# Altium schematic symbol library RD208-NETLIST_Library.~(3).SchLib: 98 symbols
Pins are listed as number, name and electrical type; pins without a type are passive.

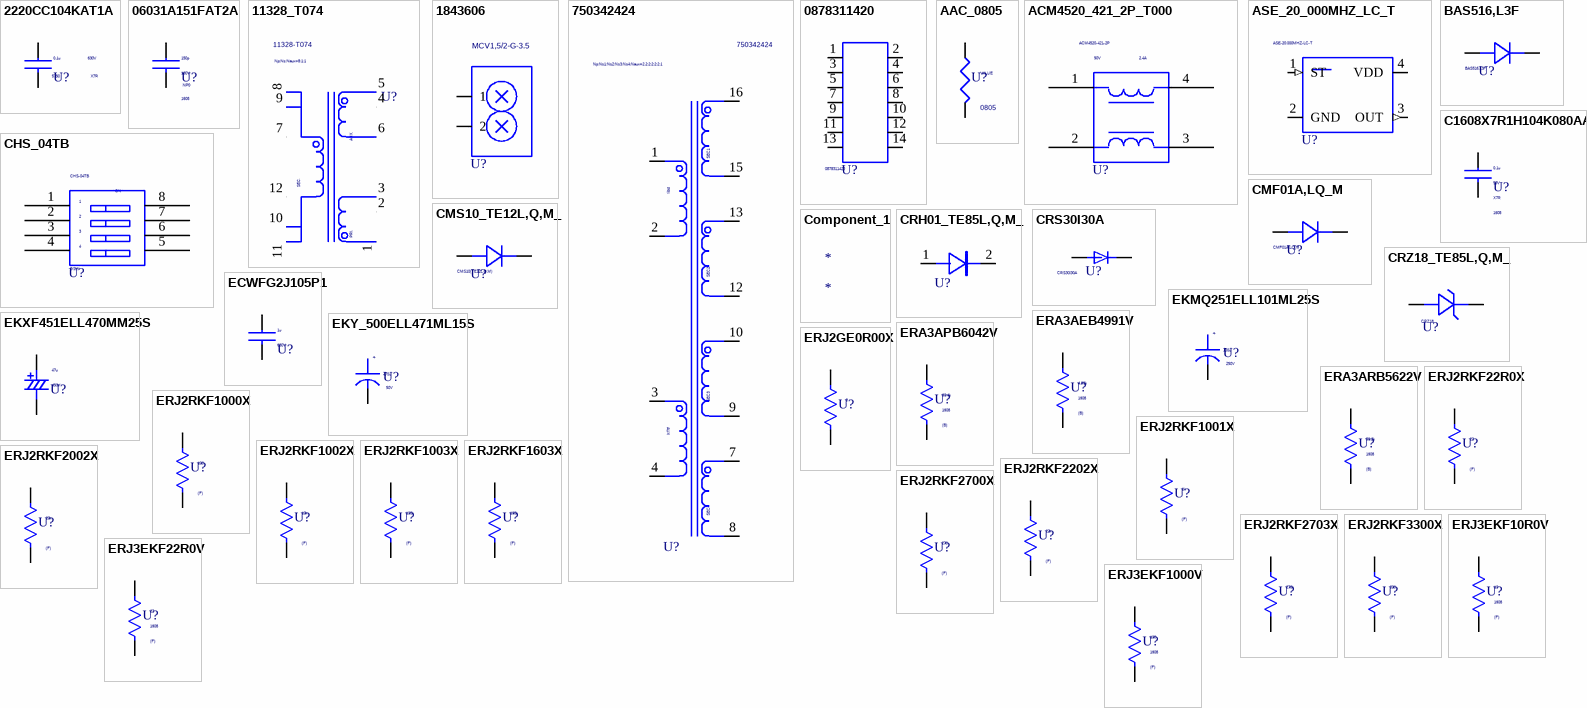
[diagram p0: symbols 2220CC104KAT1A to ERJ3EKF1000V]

## 2220CC104KAT1A
designator U?  VAL2: 630V  SIZECODESMD: 5750  VALUE4: X7R  VAL1: 0.1u  (hidden comment: 2220CC104KAT1A)
MANUFACTURER: AVX; ITEM: CAP Ceramic; TIME: 08:44:47; UPDATEUSER: t5459927; SAVECOUNT: 1; OriginalSymbolOrigin: (0,0); Altium-Right: 20; Altium-Bottom: 10
pins: 1, 2

## 06031A151FAT2A
designator U?  VAL2: 100V  SIZECODESMD: 1608  VALUE4: NP0  VAL1: 150p  (hidden comment: 06031A151FAT2A)
MANUFACTURER: AVX; ITEM: CAP Ceramic; TIME: 08:44:46; UPDATEUSER: t5459927; SAVECOUNT: 1; OriginalSymbolOrigin: (0,0); Altium-Right: 20; Altium-Bottom: 10
pins: 1, 2

## 11328_T074
designator U?  VAL2: Np:Ns:Naux=8:1:1  VAL1: 11328-T074  (hidden comment: 11328_T074)
MANUFACTURER: SUMIDA; ITEM: Transformer; TIME: 08:44:47; UPDATEUSER: PS4_common_PC; UPDATETIME: 15:04:11; SAVECOUNT: 3; SAVEAREA0: -40366,-32840,49907,8293; OriginalSymbolOrigin: (-2540,2540); Altium-Right: 60; Altium-Bottom: 120
pins: 1, 2, 3, 4, 5, 6, 7, 8, 9, 10, 11, 12

## 1843606
designator U?  SCH_NAME: MCV1,5/2-G-3.5  (hidden comment: 1843606)
MANUFACTURER: PHOENIX CONTACT; ITEM: Connector 2Pin Terminal Block; TIME: 08:44:48; UPDATEUSER: PS4_common_PC; UPDATETIME: 15:46:31; SAVECOUNT: 2; SAVEAREA0: -7641,-15544,14757,852; OriginalSymbolOrigin: (0,0); Altium-Right: 40; Altium-Bottom: 60
pins: 1, 2

## 750342424
designator U?  VAL2: Np:Ns1:Ns2:Ns3:Ns4:Naux=2.2:2:2:2:2:1  (hidden comment: 750342424)
MANUFACTURER: WURTH; ITEM: Transformer; TIME: 08:44:46; UPDATEUSER: t5459927; SAVECOUNT: 1; OriginalSymbolOrigin: (0,2540); Altium-Right: 40; Altium-Bottom: 310
pins: 1, 2, 3, 4, 7, 8, 9, 10, 12, 13, 15, 16

## 0878311420
designator U?
MANUFACTURER: Molex; ITEM: Connector; TIME: 08:44:46; UPDATEUSER: PS4_common_PC; UPDATETIME: 10:48:07; SAVECOUNT: 2; SAVEAREA0: -11456,-20726,18408,1136; OriginalSymbolOrigin: (0,0); Altium-Right: 30; Altium-Bottom: 80
pins: 1, 2, 3, 4, 5, 6, 7, 8, 9, 10, 11, 12, 13, 14

## AAC_0805
designator U?  SIZE: 0805  VAL1: VALUE  (hidden comment: AAC_0805)
7TH PART FIELD: RES.,; 4TH PART FIELD: VISHAY,; 3RD PART FIELD: CHIP; 2ND PART FIELD: 1-5%; 5TH PART FIELD: CRCW0805---RT6; 1ST PART FIELD: 1/8W; TIME: 08:44:45; UPDATEUSER: t5459927; SAVECOUNT: 1; OriginalSymbolOrigin: (0,0); Altium-Right: 20; Altium-Bottom: 30
pins: 1, 2

## ACM4520_421_2P_T000
designator U?  VAL2: 2.4A  VAL1: 50V  SCH_NAME: ACM4520-421-2P  (hidden comment: ACM4520_421_2P_T000)
MANUFACTURER: TDK; ITEM: Filter; COMP: ACM4520-421-2P-T000; TIME: 08:44:48; UPDATEUSER: PS4_common_PC; UPDATETIME: 15:46:48; SAVECOUNT: 2; SAVEAREA0: -11402,-15649,23384,1144; OriginalSymbolOrigin: (0,0); Altium-Right: 50; Altium-Bottom: 60
pins: 1 B, 2 CB, 3 PSG, 4 CG4

## ASE_20_000MHZ_LC_T
designator U?  VAL1: ASE-20.000MHZ-LC-T  (hidden comment: ASE_20_000MHZ_LC_T)
MANUFACTURER: Abracon; ITEM: Crystal  Oscillator; VAL2: 20.0MHz; SIZECODESMD: 3225; VALUE4: 50ppm; TIME: 08:44:46; UPDATEUSER: PS4_common_PC; UPDATETIME: 16:08:33; SAVECOUNT: 3; SAVEAREA0: -31083,-23837,46439,11486; OriginalSymbolOrigin: (0,0); Altium-Right: 60; Altium-Bottom: 50
pins: 1 ST (in), 2 GND, 3 OUT (out), 4 VDD

## BAS516,L3F
designator U?
MANUFACTURER: TOSHIBA; ITEM: DIODE; TIME: 08:44:45; UPDATEUSER: t5459927; SAVECOUNT: 1; OriginalSymbolOrigin: (0,0); Altium-Right: 30; Altium-Bottom: 20
pins: A ANODE, K CATHODE

## C1608X7R1H104K080AA
designator U?  VAL2: 50V  SIZECODESMD: 1608  VALUE4: X7R  VAL1: 0.1u  (hidden comment: C1608X7R1H104K080AA)
MANUFACTURER: TDK; ITEM: CAP Ceramic; TIME: 08:44:45; UPDATEUSER: t5459927; SAVECOUNT: 1; OriginalSymbolOrigin: (0,0); Altium-Right: 20; Altium-Bottom: 10
pins: 1, 2

## CHS_04TB
designator U?  VAL1: DSW  SCH_NAME: CHS-04TB  (hidden comment: CHS_04TB)
MANUFACTURER: COPAL; ITEM: DIP Switch 4P; VAL2: 50V 100mA; TIME: 08:44:46; UPDATEUSER: PS4_common_PC; UPDATETIME: 10:48:35; SAVECOUNT: 2; SAVEAREA0: -8722,-16798,20771,4793; OriginalSymbolOrigin: (0,0); Altium-Right: 50
pins: 1, 2, 3, 4, 5, 6, 7, 8

## CMF01A,LQ_M
designator U?  VAL1: CMF01A,LQ(M  (hidden comment: CMF01A,LQ_M)
MANUFACTURER: TOSHIBA; ITEM: DIODE; TIME: 08:44:46; UPDATEUSER: t5459927; SAVECOUNT: 1; OriginalSymbolOrigin: (0,0); Altium-Right: 30; Altium-Bottom: 20
pins: A ANODE, K CATHODE

## CMS10_TE12L,Q,M_
designator U?  VAL1: CMS10(TE12L,Q,M)  (hidden comment: CMS10_TE12L,Q,M_)
MANUFACTURER: TOSHIBA; ITEM: DIODE; TIME: 08:44:46; UPDATEUSER: t5459927; SAVECOUNT: 1; OriginalSymbolOrigin: (0,0); Altium-Right: 30; Altium-Bottom: 20
pins: A ANODE, K CATHODE

## Component_1
designator *

## CRH01_TE85L,Q,M_
designator U?  (value not drawn)
MANUFACTURER: TOSHIBA; ITEM: DIODE; COMP: CRH01(TE85L,Q,M); TIME: 08:44:47; UPDATEUSER: t5459927; SAVECOUNT: 1; OriginalSymbolOrigin: (0,0); Altium-Right: 30; Altium-Bottom: 20
pins: 1 A, 2 C

## CRS30I30A
designator U?
MANUFACTURER: TOSHIBA; ITEM: DIODE; TIME: 08:44:48; UPDATEUSER: t5459927; SAVECOUNT: 1; OriginalSymbolOrigin: (0,0); Altium-Right: 20
pins: A ANODE, K CATHODE

## CRZ18_TE85L,Q,M_
designator U?  VAL1: CRZ18  (hidden comment: CRZ18_TE85L,Q,M_)
MANUFACTURER: TOSHIBA; COMP: CRZ18(TE85L,Q,M); ITEM: DIODE Zener; TIME: 08:44:47; UPDATEUSER: t5459927; SAVECOUNT: 1; OriginalSymbolOrigin: (0,0); Altium-Right: 30; Altium-Bottom: 20
pins: A ANODE, K CATHODE

## ECWFG2J105P1
designator U?  VAL2: 630V  VAL1: 1u  (hidden comment: ECWFG2J105P1)
MANUFACTURER: PANASONIC; ITEM: CAP Film; TIME: 08:44:47; UPDATEUSER: t5459927; SAVECOUNT: 1; OriginalSymbolOrigin: (0,0); Altium-Right: 20; Altium-Bottom: 10
pins: 1, 2

## EKMQ251ELL101ML25S
designator U?  VAL2: 250V  VAL1: 100u  (hidden comment: EKMQ251ELL101ML25S)
MANUFACTURER: Nippon Chemi-Con; ITEM: CAP ALUM; TIME: 08:44:45; UPDATEUSER: t5459927; SAVECOUNT: 1; OriginalSymbolOrigin: (0,2540); Altium-Right: 20
pins: 1, 2

## EKXF451ELL470MM25S
designator U?  VAL2: 450V  VAL1: 47u  (hidden comment: EKXF451ELL470MM25S)
MANUFACTURER: Nippon Chemi-Con; ITEM: CAP ALUM; SIZECODESMD: 18.0mm; TIME: 08:44:46; UPDATEUSER: t5459927; SAVECOUNT: 1; OriginalSymbolOrigin: (0,0); Altium-Right: 20
pins: 1, 2

## EKY_500ELL471ML15S
designator U?  VAL2: 50V  VAL1: 470u  (hidden comment: EKY_500ELL471ML15S)
MANUFACTURER: Nippon Chemi-Con; ITEM: CAP ALUM; SIZECODESMD: 16.0mm; COMP: EKY-500ELL471ML15S; TIME: 08:44:47; UPDATEUSER: t5459927; SAVECOUNT: 1; OriginalSymbolOrigin: (0,2540); Altium-Right: 20
pins: 1, 2

## ERA3AEB4991V
designator U?  SIZECODESMD: 1608  VALUE4: (B)  VAL1: 4.99k  (hidden comment: ERA3AEB4991V)
MANUFACTURER: Panasonic; ITEM: Register; VAL2: 1/10W; TIME: 08:44:47; UPDATEUSER: t5459927; SAVECOUNT: 1; OriginalSymbolOrigin: (0,0); Altium-Right: 20; Altium-Bottom: 30
pins: 1, 2

## ERA3APB6042V
designator U?  SIZECODESMD: 1608  VAL1: 60.4k  VLUE4: (B)  (hidden comment: ERA3APB6042V)
MANUFACTURER: Panasonic; ITEM: Register; VAL2: 1/10W; TIME: 08:44:47; UPDATEUSER: t5459927; SAVECOUNT: 1; OriginalSymbolOrigin: (0,0); Altium-Right: 20; Altium-Bottom: 30
pins: 1, 2

## ERA3ARB5622V
designator U?  SIZECODESMD: 1608  VALUE4: (B)  VAL1: 56.2k  (hidden comment: ERA3ARB5622V)
MANUFACTURER: Panasonic; ITEM: Register; VAL2: 1/10W; TIME: 08:44:47; UPDATEUSER: t5459927; SAVECOUNT: 1; OriginalSymbolOrigin: (0,0); Altium-Right: 20; Altium-Bottom: 30
pins: 1, 2

## ERJ2GE0R00X
designator U?  VAL1: 0  (hidden comment: ERJ2GE0R00X)
MANUFACTURER: Panasonic; ITEM: Register; VAL2: 1/10W; SIZECODESMD: 1005; TIME: 08:44:45; UPDATEUSER: t5459927; SAVECOUNT: 1; OriginalSymbolOrigin: (0,0); Altium-Right: 20; Altium-Bottom: 30
pins: 1, 2

## ERJ2RKF22R0X
designator U?  VALUE4: (F)  VAL1: 22  (hidden comment: ERJ2RKF22R0X)
MANUFACTURER: Panasonic; ITEM: Register; VAL2: 1/10W; SIZECODESMD: 1005; TIME: 08:44:46; UPDATEUSER: t5459927; SAVECOUNT: 1; OriginalSymbolOrigin: (0,0); Altium-Right: 20; Altium-Bottom: 30
pins: 1, 2

## ERJ2RKF1000X
designator U?  VALUE4: (F)  VAL1: 100  (hidden comment: ERJ2RKF1000X)
MANUFACTURER: Panasonic; ITEM: Register; VAL2: 1/10W; SIZECODESMD: 1005; TIME: 08:44:46; UPDATEUSER: t5459927; SAVECOUNT: 1; OriginalSymbolOrigin: (0,0); Altium-Right: 20; Altium-Bottom: 30
pins: 1, 2

## ERJ2RKF1001X
designator U?  VALUE4: (F)  VAL1: 1k  (hidden comment: ERJ2RKF1001X)
MANUFACTURER: Panasonic; ITEM: Register; VAL2: 1/10W; SIZECODESMD: 1005; TIME: 08:44:45; UPDATEUSER: t5459927; SAVECOUNT: 1; OriginalSymbolOrigin: (0,0); Altium-Right: 20; Altium-Bottom: 30
pins: 1, 2

## ERJ2RKF1002X
designator U?  VALUE4: (F)  VAL1: 10k  (hidden comment: ERJ2RKF1002X)
MANUFACTURER: Panasonic; ITEM: Register; VAL2: 1/10W; SIZECODESMD: 1005; TIME: 08:44:45; UPDATEUSER: t5459927; SAVECOUNT: 1; OriginalSymbolOrigin: (0,0); Altium-Right: 20; Altium-Bottom: 30
pins: 1, 2

## ERJ2RKF1003X
designator U?  VALUE4: (F)  VAL1: 100k  (hidden comment: ERJ2RKF1003X)
MANUFACTURER: Panasonic; ITEM: Register; VAL2: 1/10W; SIZECODESMD: 1005; TIME: 08:44:47; UPDATEUSER: t5459927; SAVECOUNT: 1; OriginalSymbolOrigin: (0,0); Altium-Right: 20; Altium-Bottom: 30
pins: 1, 2

## ERJ2RKF1603X
designator U?  VALUE4: (F)  VAL1: 160k  (hidden comment: ERJ2RKF1603X)
MANUFACTURER: Panasonic; ITEM: Register; VAL2: 1/10W; SIZECODESMD: 1005; TIME: 08:44:47; UPDATEUSER: t5459927; SAVECOUNT: 1; OriginalSymbolOrigin: (0,0); Altium-Right: 20; Altium-Bottom: 30
pins: 1, 2

## ERJ2RKF2002X
designator U?  VALUE4: (F)  VAL1: 20k  (hidden comment: ERJ2RKF2002X)
MANUFACTURER: Panasonic; ITEM: Register; VAL2: 1/10W; SIZECODESMD: 1005; TIME: 08:44:45; UPDATEUSER: t5459927; SAVECOUNT: 1; OriginalSymbolOrigin: (0,0); Altium-Right: 20; Altium-Bottom: 30
pins: 1, 2

## ERJ2RKF2202X
designator U?  VALUE4: (F)  VAL1: 22k  (hidden comment: ERJ2RKF2202X)
MANUFACTURER: Panasonic; ITEM: Register; VAL2: 1/10W; SIZECODESMD: 1005; TIME: 08:44:47; UPDATEUSER: t5459927; SAVECOUNT: 1; OriginalSymbolOrigin: (0,0); Altium-Right: 20; Altium-Bottom: 30
pins: 1, 2

## ERJ2RKF2700X
designator U?  VALUE4: (F)  VAL1: 270  (hidden comment: ERJ2RKF2700X)
MANUFACTURER: Panasonic; ITEM: Register; VAL2: 1/10W; SIZECODESMD: 1005; TIME: 08:44:45; UPDATEUSER: t5459927; SAVECOUNT: 1; OriginalSymbolOrigin: (0,0); Altium-Right: 20; Altium-Bottom: 30
pins: 1, 2

## ERJ2RKF2703X
designator U?  VALUE4: (F)  VAL1: 270k  (hidden comment: ERJ2RKF2703X)
MANUFACTURER: Panasonic; ITEM: Register; VAL2: 1/10W; SIZECODESMD: 1005; TIME: 08:44:47; UPDATEUSER: t5459927; SAVECOUNT: 1; OriginalSymbolOrigin: (0,0); Altium-Right: 20; Altium-Bottom: 30
pins: 1, 2

## ERJ2RKF3300X
designator U?  VALUE4: (F)  VAL1: 330  (hidden comment: ERJ2RKF3300X)
MANUFACTURER: Panasonic; ITEM: Register; VAL2: 1/10W; SIZECODESMD: 1005; TIME: 08:44:47; UPDATEUSER: t5459927; SAVECOUNT: 1; OriginalSymbolOrigin: (0,0); Altium-Right: 20; Altium-Bottom: 30
pins: 1, 2

## ERJ3EKF10R0V
designator U?  SIZECODESMD: 1608  VALUE4: (F)  VAL1: 10  (hidden comment: ERJ3EKF10R0V)
MANUFACTURER: Panasonic; ITEM: Register; VAL2: 1/10W; TIME: 08:44:45; UPDATEUSER: t5459927; SAVECOUNT: 1; OriginalSymbolOrigin: (0,0); Altium-Right: 20; Altium-Bottom: 30
pins: 1, 2

## ERJ3EKF22R0V
designator U?  SIZECODESMD: 1608  VALUE4: (F)  VAL1: 22  (hidden comment: ERJ3EKF22R0V)
MANUFACTURER: Panasonic; ITEM: Register; VAL2: 1/10W; TIME: 08:44:45; UPDATEUSER: t5459927; SAVECOUNT: 1; OriginalSymbolOrigin: (0,0); Altium-Right: 20; Altium-Bottom: 30
pins: 1, 2

## ERJ3EKF1000V
designator U?  SIZECODESMD: 1608  VALUE4: (F)  VAL1: 100  (hidden comment: ERJ3EKF1000V)
MANUFACTURER: Panasonic; ITEM: Register; VAL2: 1/10W; TIME: 08:44:47; UPDATEUSER: t5459927; SAVECOUNT: 1; OriginalSymbolOrigin: (0,0); Altium-Right: 20; Altium-Bottom: 30
pins: 1, 2

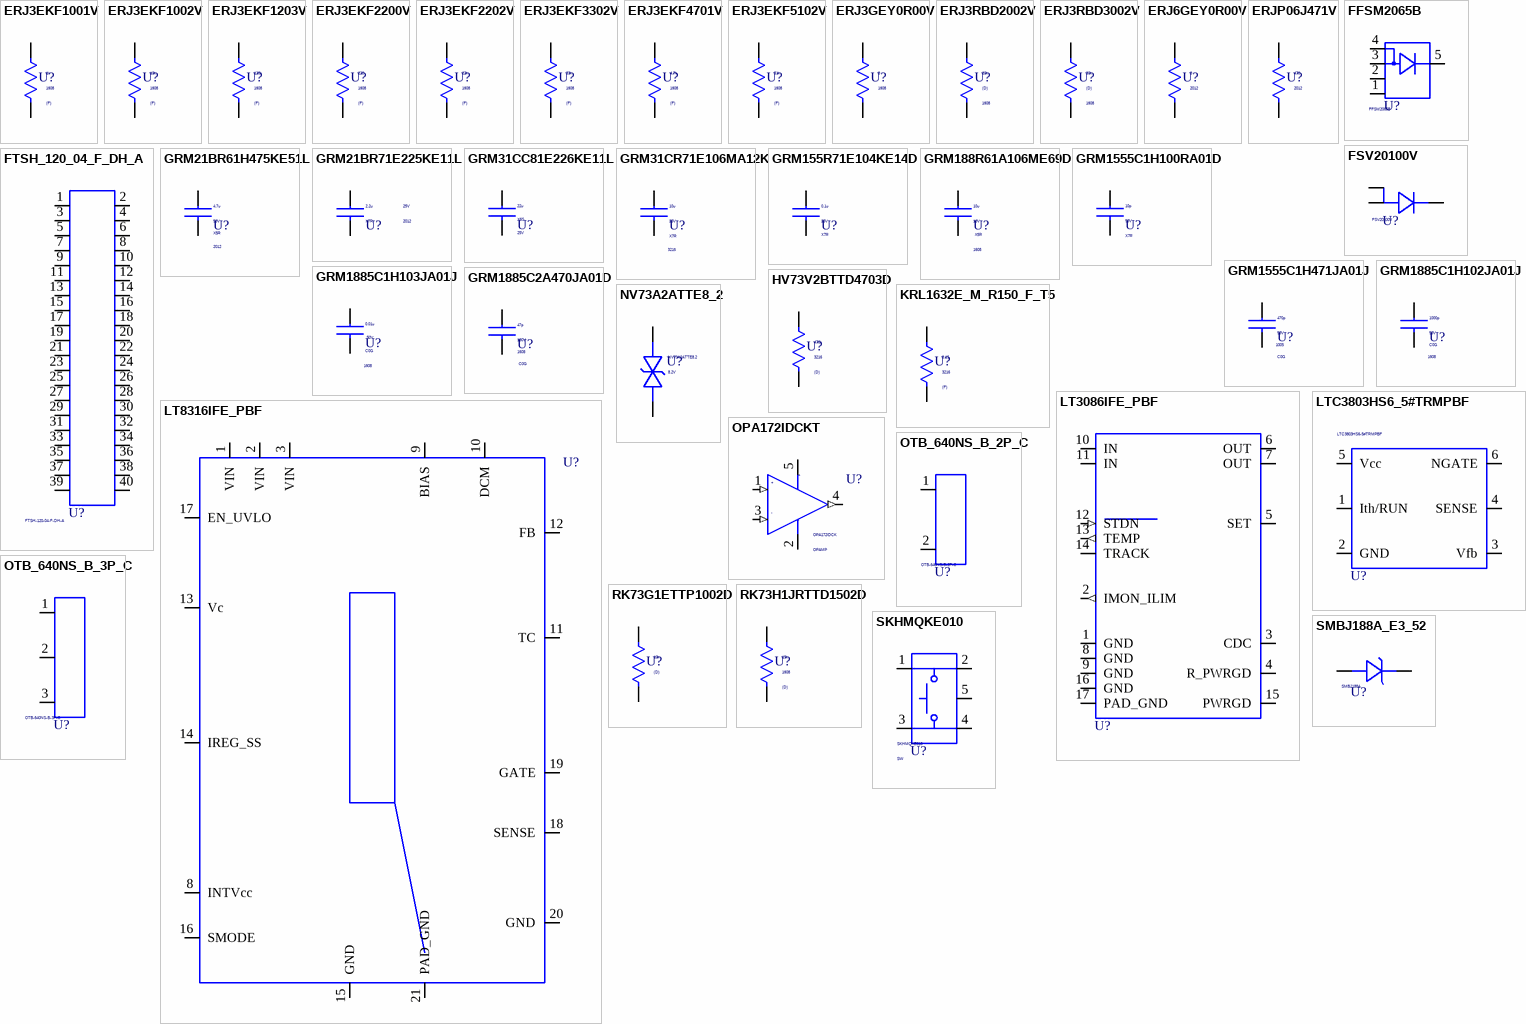
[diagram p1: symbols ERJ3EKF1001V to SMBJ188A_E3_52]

## ERJ3EKF1001V
designator U?  SIZECODESMD: 1608  VALUE4: (F)  VAL1: 1k  (hidden comment: ERJ3EKF1001V)
MANUFACTURER: Panasonic; ITEM: Register; VAL2: 1/10W; TIME: 08:44:46; UPDATEUSER: t5459927; SAVECOUNT: 1; OriginalSymbolOrigin: (0,0); Altium-Right: 20; Altium-Bottom: 30
pins: 1, 2

## ERJ3EKF1002V
designator U?  SIZECODESMD: 1608  VALUE4: (F)  VAL1: 10k  (hidden comment: ERJ3EKF1002V)
MANUFACTURER: Panasonic; ITEM: Register; VAL2: 1/10W; TIME: 08:44:46; UPDATEUSER: t5459927; SAVECOUNT: 1; OriginalSymbolOrigin: (0,0); Altium-Right: 20; Altium-Bottom: 30
pins: 1, 2

## ERJ3EKF1203V
designator U?  SIZECODESMD: 1608  VALUE4: (F)  VAL1: 120k  (hidden comment: ERJ3EKF1203V)
MANUFACTURER: Panasonic; ITEM: Register; VAL2: 1/10W; TIME: 08:44:47; UPDATEUSER: t5459927; SAVECOUNT: 1; OriginalSymbolOrigin: (0,0); Altium-Right: 20; Altium-Bottom: 30
pins: 1, 2

## ERJ3EKF2200V
designator U?  SIZECODESMD: 1608  VALUE4: (F)  VAL1: 220  (hidden comment: ERJ3EKF2200V)
MANUFACTURER: Panasonic; ITEM: Register; VAL2: 1/10W; TIME: 08:44:46; UPDATEUSER: t5459927; SAVECOUNT: 1; OriginalSymbolOrigin: (0,0); Altium-Right: 20; Altium-Bottom: 30
pins: 1, 2

## ERJ3EKF2202V
designator U?  SIZECODESMD: 1608  VALUE4: (F)  VAL1: 22k  (hidden comment: ERJ3EKF2202V)
MANUFACTURER: Panasonic; ITEM: Register; VAL2: 1/10W; TIME: 08:44:46; UPDATEUSER: t5459927; SAVECOUNT: 1; OriginalSymbolOrigin: (0,0); Altium-Right: 20; Altium-Bottom: 30
pins: 1, 2

## ERJ3EKF3302V
designator U?  SIZECODESMD: 1608  VALUE4: (F)  VAL1: 33k  (hidden comment: ERJ3EKF3302V)
MANUFACTURER: Panasonic; ITEM: Register; VAL2: 1/10W; TIME: 08:44:46; UPDATEUSER: t5459927; SAVECOUNT: 1; OriginalSymbolOrigin: (0,0); Altium-Right: 20; Altium-Bottom: 30
pins: 1, 2

## ERJ3EKF4701V
designator U?  SIZECODESMD: 1608  VALUE4: (F)  VAL1: 4.7k  (hidden comment: ERJ3EKF4701V)
MANUFACTURER: Panasonic; ITEM: Register; VAL2: 1/10W; TIME: 08:44:46; UPDATEUSER: t5459927; SAVECOUNT: 1; OriginalSymbolOrigin: (0,0); Altium-Right: 20; Altium-Bottom: 30
pins: 1, 2

## ERJ3EKF5102V
designator U?  SIZECODESMD: 1608  VALUE4: (F)  VAL1: 51k  (hidden comment: ERJ3EKF5102V)
MANUFACTURER: Panasonic; ITEM: Register; VAL2: 1/10W; TIME: 08:44:46; UPDATEUSER: t5459927; SAVECOUNT: 1; OriginalSymbolOrigin: (0,0); Altium-Right: 20; Altium-Bottom: 30
pins: 1, 2

## ERJ3GEY0R00V
designator U?  SIZECODESMD: 1608  VAL1: 0  (hidden comment: ERJ3GEY0R00V)
MANUFACTURER: Panasonic; ITEM: Register; VAL2: 1/10W; TIME: 08:44:45; UPDATEUSER: t5459927; SAVECOUNT: 1; OriginalSymbolOrigin: (0,0); Altium-Right: 20; Altium-Bottom: 30
pins: 1, 2

## ERJ3RBD2002V
designator U?  SIZECODESMD: 1608  VALUE4: (D)  VAL1: 20k  (hidden comment: ERJ3RBD2002V)
MANUFACTURER: Panasonic; ITEM: Register; VAL2: 1/10W; TIME: 08:44:45; UPDATEUSER: t5459927; SAVECOUNT: 1; OriginalSymbolOrigin: (0,0); Altium-Right: 20; Altium-Bottom: 30
pins: 1, 2

## ERJ3RBD3002V
designator U?  SIZECODESMD: 1608  VALUE4: (D)  VAL1: 30k  (hidden comment: ERJ3RBD3002V)
MANUFACTURER: Panasonic; ITEM: Register; VAL2: 1/10W; TIME: 08:44:45; UPDATEUSER: t5459927; SAVECOUNT: 1; OriginalSymbolOrigin: (0,0); Altium-Right: 20; Altium-Bottom: 30
pins: 1, 2

## ERJ6GEY0R00V
designator U?  SIZECODESMD: 2012  VAL1: 0  (hidden comment: ERJ6GEY0R00V)
MANUFACTURER: Panasonic; ITEM: Register; VAL2: 1/10W; TIME: 08:44:47; UPDATEUSER: t5459927; SAVECOUNT: 1; OriginalSymbolOrigin: (0,0); Altium-Right: 20; Altium-Bottom: 30
pins: 1, 2

## ERJP06J471V
designator U?  SIZECODESMD: 2012  VAL1: 470  (hidden comment: ERJP06J471V)
MANUFACTURER: Panasonic; ITEM: Register; VAL2: 1/2W; VALUE4: (J); TIME: 08:44:46; UPDATEUSER: t5459927; SAVECOUNT: 1; OriginalSymbolOrigin: (0,0); Altium-Right: 20; Altium-Bottom: 30
pins: 1, 2

## FFSM2065B
designator U?
MANUFACTURER: ON_SEMI; ITEM: DIODE; TIME: 08:44:45; UPDATEUSER: PS4_common_PC; UPDATETIME: 10:49:22; SAVECOUNT: 2; SAVEAREA0: -3235,-11101,10576,-990; OriginalSymbolOrigin: (0,0); Altium-Right: 30; Altium-Bottom: 50
pins: 1 NC1, 2 NC2, 3 ANODE3, 4 ANODE4, 5 CATHODE

## FSV20100V
designator U?
MANUFACTURER: On semiconductor; ITEM: DIODE; TIME: 08:44:47; UPDATEUSER: t5459927; SAVECOUNT: 1; OriginalSymbolOrigin: (0,2540); Altium-Right: 30
pins: 1 ANODE-1, 2 ANODE-2, 3 CATHODE

## FTSH_120_04_F_DH_A
designator U?  VAL1: FTSH-120-04-F-DH-A  (hidden comment: FTSH_120_04_F_DH_A)
MANUFACTURER: Samtec; ITEM: Connector; TIME: 08:44:46; UPDATEUSER: PS4_common_PC; UPDATETIME: 15:47:32; SAVECOUNT: 2; SAVEAREA0: -36272,-54408,42126,2984; OriginalSymbolOrigin: (0,0); Altium-Right: 30; Altium-Bottom: 210
pins: 1, 2, 3, 4, 5, 6, 7, 8, 9, 10, 11, 12, 13, 14, 15, 16, 17, 18, 19, 20, 21, 22, 23, 24, 25, 26, 27, 28, 29, 30, 31, 32, 33, 34, 35, 36, 37, 38, 39, 40

## GRM21BR61H475KE51L
designator U?  VAL2: 50V  SIZECODESMD: 2012  VALUE4: X5R  VAL1: 4.7u  (hidden comment: GRM21BR61H475KE51L)
MANUFACTURER: MURATA; ITEM: CAP Ceramic; TIME: 08:44:46; UPDATEUSER: t5459927; SAVECOUNT: 1; OriginalSymbolOrigin: (0,0); Altium-Right: 20; Altium-Bottom: 10
pins: 1, 2

## GRM21BR71E225KE11L
designator U?  VAL2: 25V  SIZECODESMD: 2012  VALUE4: X7R  VAL1: 2.2u  (hidden comment: GRM21BR71E225KE11L)
MANUFACTURER: MURATA; ITEM: CAP Ceramic; TIME: 08:44:45; UPDATEUSER: t5459927; SAVECOUNT: 1; OriginalSymbolOrigin: (0,0); Altium-Right: 20; Altium-Bottom: 10
pins: 1, 2

## GRM31CC81E226KE11L
designator U?  VAL2: 25V  VALUE4: X6S  VAL1: 22u  (hidden comment: GRM31CC81E226KE11L)
MANUFACTURER: MURATA; ITEM: CAP Ceramic; SIZECODESMD: 3216; TIME: 08:44:47; UPDATEUSER: t5459927; SAVECOUNT: 1; OriginalSymbolOrigin: (0,0); Altium-Right: 20; Altium-Bottom: 10
pins: 1, 2

## GRM31CR71E106MA12K
designator U?  VAL2: 25V  SIZECODESMD: 3216  VALUE4: X7R  VAL1: 10u  (hidden comment: GRM31CR71E106MA12K)
MANUFACTURER: MURATA; ITEM: CAP Ceramic; TIME: 08:44:46; UPDATEUSER: t5459927; SAVECOUNT: 1; OriginalSymbolOrigin: (0,0); Altium-Right: 20; Altium-Bottom: 10
pins: 1, 2

## GRM155R71E104KE14D
designator U?  VAL2: 25V  VALUE4: X7R  VAL1: 0.1u  (hidden comment: GRM155R71E104KE14D)
MANUFACTURER: MURATA; ITEM: CAP Ceramic; SIZECODESMD: 1005; TIME: 08:44:45; UPDATEUSER: t5459927; SAVECOUNT: 1; OriginalSymbolOrigin: (0,0); Altium-Right: 20; Altium-Bottom: 10
pins: 1, 2

## GRM188R61A106ME69D
designator U?  VAL2: 10V  SIZECODESMD: 1608  VALUE4: X5R  VAL1: 10u  (hidden comment: GRM188R61A106ME69D)
MANUFACTURER: MURATA; ITEM: CAP Ceramic; TIME: 08:44:46; UPDATEUSER: t5459927; SAVECOUNT: 1; OriginalSymbolOrigin: (0,0); Altium-Right: 20; Altium-Bottom: 10
pins: 1, 2

## GRM1555C1H100RA01D
designator U?  VAL2: 50V  VALUE4: X7R  VAL1: 10p  (hidden comment: GRM1555C1H100RA01D)
MANUFACTURER: MURATA; ITEM: CAP Ceramic; SIZECODESMD: 1005; TIME: 08:44:45; UPDATEUSER: t5459927; SAVECOUNT: 1; OriginalSymbolOrigin: (0,0); Altium-Right: 20; Altium-Bottom: 10
pins: 1, 2

## GRM1555C1H471JA01J
designator U?  VAL2: 50V  SIZECODESMD: 1005  VALUE4: C0G  VAL1: 470p  (hidden comment: GRM1555C1H471JA01J)
MANUFACTURER: MURATA; ITEM: CAP Ceramic; TIME: 08:44:46; UPDATEUSER: t5459927; SAVECOUNT: 1; OriginalSymbolOrigin: (0,0); Altium-Right: 20; Altium-Bottom: 10
pins: 1, 2

## GRM1885C1H102JA01J
designator U?  VAL2: 50V  SIZECODESMD: 1608  VALUE4: C0G  VAL1: 1000p  (hidden comment: GRM1885C1H102JA01J)
MANUFACTURER: MURATA; ITEM: CAP Ceramic; TIME: 08:44:47; UPDATEUSER: t5459927; SAVECOUNT: 1; OriginalSymbolOrigin: (0,0); Altium-Right: 20; Altium-Bottom: 10
pins: 1, 2

## GRM1885C1H103JA01J
designator U?  VAL2: 50V  SIZECODESMD: 1608  VALUE4: C0G  VAL1: 0.01u  (hidden comment: GRM1885C1H103JA01J)
MANUFACTURER: MURATA; ITEM: CAP Ceramic; TIME: 08:44:46; UPDATEUSER: t5459927; SAVECOUNT: 1; OriginalSymbolOrigin: (0,0); Altium-Right: 20; Altium-Bottom: 10
pins: 1, 2

## GRM1885C2A470JA01D
designator U?  VAL2: 100V  SIZECODESMD: 1608  VALUE4: C0G  VAL1: 47p  (hidden comment: GRM1885C2A470JA01D)
MANUFACTURER: MURATA; ITEM: CAP Ceramic; TIME: 08:44:47; UPDATEUSER: t5459927; SAVECOUNT: 1; OriginalSymbolOrigin: (0,0); Altium-Right: 20; Altium-Bottom: 10
pins: 1, 2

## HV73V2BTTD4703D
designator U?  SIZECODESMD: 3216  VALUE4: (D)  VAL1: 470k  (hidden comment: HV73V2BTTD4703D)
MANUFACTURER: KOA; ITEM: Register; VAL2: 1/4W; TIME: 08:44:45; UPDATEUSER: t5459927; SAVECOUNT: 1; OriginalSymbolOrigin: (0,0); Altium-Right: 20; Altium-Bottom: 30
pins: 1, 2

## KRL1632E_M_R150_F_T5
designator U?  SIZECODESMD: 3216  VALUE4: (F)  VAL1: 0.15  (hidden comment: KRL1632E_M_R150_F_T5)
MANUFACTURER: Susumu; ITEM: Register; VAL2: 3/4W; COMP: KRL1632E-M-R150-F-T5; TIME: 08:44:47; UPDATEUSER: t5459927; SAVECOUNT: 1; OriginalSymbolOrigin: (0,0); Altium-Right: 20; Altium-Bottom: 30
pins: 1, 2

## LT3086IFE_PBF
designator U?  (value not drawn)
MANUFACTURER: Analog Devices; ITEM: LDO; TIME: 08:44:47; UPDATEUSER: PS4_common_PC; UPDATETIME: 14:21:05; SAVECOUNT: 5; SAVEAREA0: -46534,-51518,75335,4012; OriginalSymbolOrigin: (0,0); Altium-Right: 110; Altium-Bottom: 190
pins: 1 GND, 2 IMON_ILIM (out), 3 CDC, 4 R_PWRGD, 5 SET, 6 OUT, 7 OUT, 8 GND, 9 GND, 10 IN, 11 IN, 12 STDN (in), 13 TEMP (out), 14 TRACK, 15 PWRGD, 16 GND, 17 PAD_GND

## LT8316IFE_PBF
designator U?  (value not drawn)
MANUFACTURER: Analog Devices; ITEM: IC DCDC; TIME: 08:44:47; UPDATEUSER: PS4_common_PC; UPDATETIME: 14:20:20; SAVECOUNT: 5; SAVEAREA0: -89670,-104109,148818,4559; OriginalSymbolOrigin: (0,0); Altium-Right: 230; Altium-Bottom: 350
pins: 1 VIN, 2 VIN, 3 VIN, 8 INTVcc, 9 BIAS, 10 DCM, 11 TC, 12 FB, 13 Vc, 14 IREG_SS, 15 GND, 16 SMODE, 17 EN_UVLO, 18 SENSE, 19 GATE, 20 GND, 21 PAD_GND

## LTC3803HS6_5#TRMPBF
designator U?  VAL1: LTC3803HS6-5#TRMPBF  (hidden comment: LTC3803HS6_5#TRMPBF)
MANUFACTURER: Analog Devices; ITEM: IC DCDC; VAL2: DCDC CONTROLLER; TIME: 08:44:46; UPDATEUSER: PS4_common_PC; UPDATETIME: 15:55:48; SAVECOUNT: 3; SAVEAREA0: -42732,-39864,65274,9349; OriginalSymbolOrigin: (0,0); Altium-Right: 90; Altium-Bottom: 80
pins: 1 Ith/RUN, 2 GND, 3 Vfb, 4 SENSE, 5 Vcc, 6 NGATE

## NV73A2ATTE8_2
designator U?  VAL2: 8.2V  VAL1: NV73A2ATTE8.2  (hidden comment: NV73A2ATTE8_2)
MANUFACTURER: KOA; ITEM: Varistor 8.2V; SIZECODESMD: 2012; TIME: 08:44:47; UPDATEUSER: t5459927; SAVECOUNT: 1; OriginalSymbolOrigin: (0,0); Altium-Right: 20; Altium-Bottom: 40
pins: 1 A, 2 C

## OPA172IDCKT
designator U?  VAL2: OPAMP  VAL1: OPA172IDCK  (hidden comment: OPA172IDCKT)
MANUFACTURER: TI; ITEM: Operational Amplifier; ORDER: 0; TIME: 08:44:45; UPDATEUSER: t5459927; SAVECOUNT: 1; OriginalSymbolOrigin: (0,0); Altium-Right: 40
pins: 1 +IN (in), 2 -V, 3 -IN (in), 4 OUT (out), 5 +V

## OTB_640NS_B_2P_C
designator U?  VAL1: OTB-640NS-B-2P-C  (hidden comment: OTB_640NS_B_2P_C)
MANUFACTURER: OSADA; ITEM: Connector; VAL2: 11mm   x2; TIME: 08:44:47; UPDATEUSER: PS4_common_PC; UPDATETIME: 15:39:44; SAVECOUNT: 2; SAVEAREA0: -10166,-15544,12232,852; OriginalSymbolOrigin: (0,0); Altium-Right: 20; Altium-Bottom: 60
pins: 1, 2

## OTB_640NS_B_3P_C
designator U?  VAL1: OTB-640NS-B-3P-C  (hidden comment: OTB_640NS_B_3P_C)
MANUFACTURER: OSADA; ITEM: Connector; VAL2: 11mm   x3; TIME: 08:44:46; UPDATEUSER: PS4_common_PC; UPDATETIME: 15:40:04; SAVECOUNT: 2; SAVEAREA0: -13992,-20726,15872,1136; OriginalSymbolOrigin: (0,0); Altium-Right: 20; Altium-Bottom: 80
pins: 1, 2, 3

## RK73G1ETTP1002D
designator U?  VALUE4: (D)  VAL1: 10k  (hidden comment: RK73G1ETTP1002D)
MANUFACTURER: KOA; ITEM: Register; VAL2: 1/10W; SIZECODESMD: 1005; TIME: 08:44:46; UPDATEUSER: t5459927; SAVECOUNT: 1; OriginalSymbolOrigin: (0,0); Altium-Right: 20; Altium-Bottom: 30
pins: 1, 2

## RK73H1JRTTD1502D
designator U?  SIZECODESMD: 1608  VALUE4: (D)  VAL1: 15k  (hidden comment: RK73H1JRTTD1502D)
MANUFACTURER: KOA; ITEM: Register; VAL2: 1/10W; TIME: 08:44:47; UPDATEUSER: t5459927; SAVECOUNT: 1; OriginalSymbolOrigin: (0,0); Altium-Right: 20; Altium-Bottom: 30
pins: 1, 2

## SKHMQKE010
designator U?  VAL2: SW  (hidden comment: SKHMQKE010)
MANUFACTURER: ALPS; ITEM: Tactile Switch SMD; TIME: 08:44:46; UPDATEUSER: t5459927; SAVECOUNT: 1; OriginalSymbolOrigin: (0,0); Altium-Right: 30; Altium-Bottom: 60
pins: 1, 2, 3, 4, 5

## SMBJ188A_E3_52
designator U?  VAL1: SMBJ188A  (hidden comment: SMBJ188A_E3_52)
MANUFACTURER: Vishay; COMP: SMBJ188A-E3/52; ITEM: DIODE TVS; TIME: 08:44:47; UPDATEUSER: t5459927; SAVECOUNT: 1; OriginalSymbolOrigin: (0,0); Altium-Right: 30; Altium-Bottom: 20
pins: A ANODE, K CATHODE

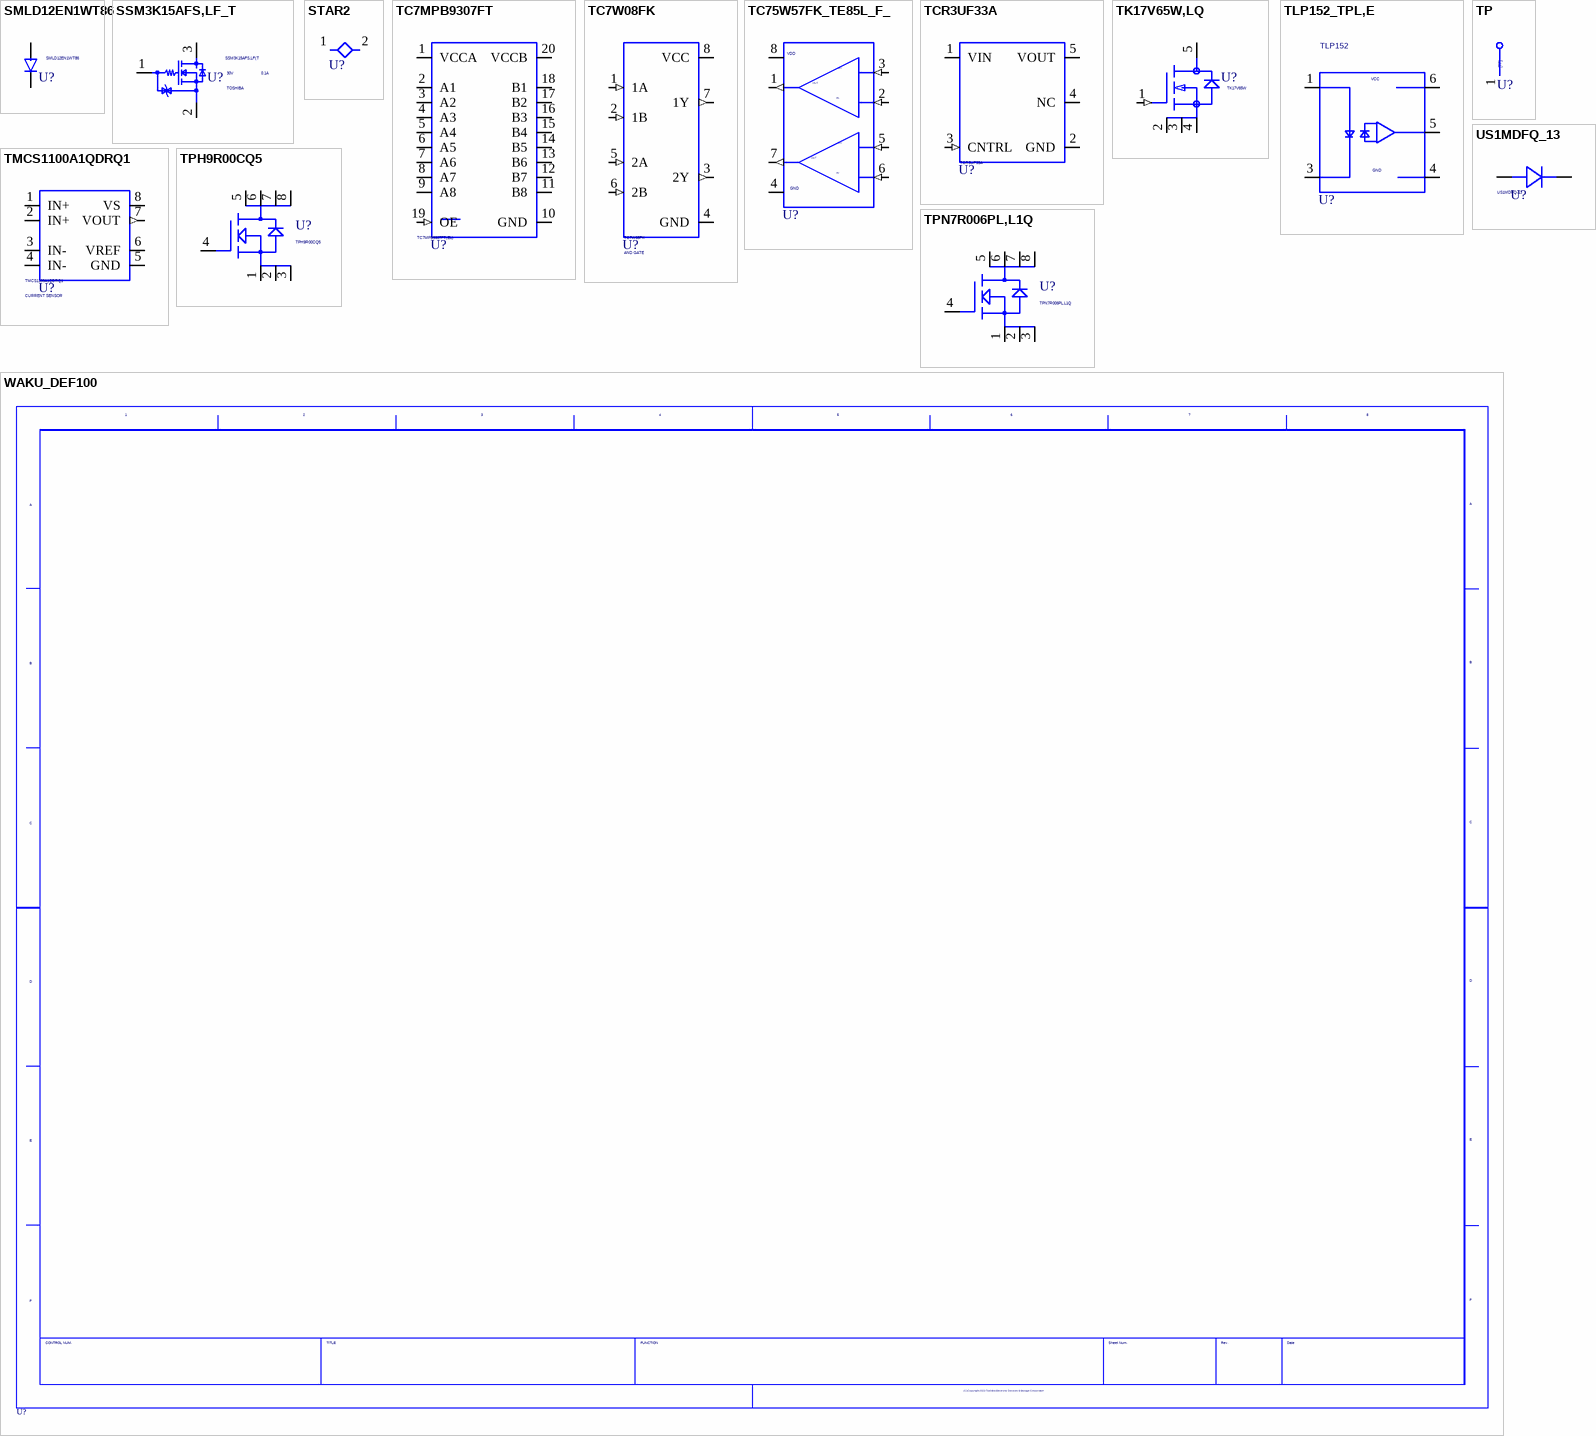
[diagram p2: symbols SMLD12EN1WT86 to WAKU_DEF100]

## SMLD12EN1WT86
designator U?
MANUFACTURER: ROHM; ITEM: LED; VAL2: GREEN; SIZECODESMD: 1608; TIME: 08:44:46; UPDATEUSER: t5459927; SAVECOUNT: 1; OriginalSymbolOrigin: (0,0); Altium-Right: 20; Altium-Bottom: 10
pins: A, K C

## SSM3K15AFS,LF_T
designator U?  VAL2: 0.1A  MANUFACTURER: TOSHIBA  SIZECODESMD: 30V  VAL1: SSM3K15AFS,LF(T  (hidden comment: SSM3K15AFS,LF_T)
ITEM: Digital Transistor NPN; ORDER: 0; TIME: 08:44:45; UPDATEUSER: t5459927; SAVECOUNT: 1; OriginalSymbolOrigin: (0,0); Altium-Right: 40; Altium-Bottom: 30
pins: 1 B, 2 E, 3 C

## STAR2
designator U?  (value not drawn)
TIME: 12:37:47; UPDATEUSER: d5009410; UPDATETIME: 12:51:51; SAVECOUNT: 17; SAVEAREA0: -6564,-5245,9999,5672; OriginalSymbolOrigin: (-2540,2540); Altium-Right: 20
pins: 1, 2

## TC7MPB9307FT
designator U?  VAL1: TC7MPB9307FT(EL)  (hidden comment: TC7MPB9307FT)
MANUFACTURER: TOSHIBA; ITEM: IC BUS SW; VAL2: BUS SW; TIME: 08:44:46; UPDATEUSER: PS4_common_PC; UPDATETIME: 15:59:21; SAVECOUNT: 4; SAVEAREA0: -17429,-46731,34553,-8676; OriginalSymbolOrigin: (0,0); Altium-Right: 70; Altium-Bottom: 130
pins: 1 VCCA, 2 A1, 3 A2, 4 A3, 5 A4, 6 A5, 7 A6, 8 A7, 9 A8, 10 GND, 11 B8, 12 B7, 13 B6, 14 B5, 15 B4, 16 B3, 17 B2, 18 B1, 19 OE (in), 20 VCCB

## TC7W08FK
designator U?  VAL2: AND GATE  (hidden comment: TC7W08FK)
MANUFACTURER: TOSHIBA; ITEM: IC Logic; TIME: 08:44:45; UPDATEUSER: PS4_common_PC; UPDATETIME: 15:42:32; SAVECOUNT: 2; SAVEAREA0: -18404,-33681,30128,1847; OriginalSymbolOrigin: (0,0); Altium-Right: 50; Altium-Bottom: 130
pins: 1 1A (in), 2 1B (in), 3 2Y (out), 4 GND, 5 2A (in), 6 2B (in), 7 1Y (out), 8 VCC

## TC75W57FK_TE85L_F_
designator U?  (value not drawn)
MANUFACTURER: TOSHIBA; ITEM: IC Comparator; VAL2: COMPARATOR; COMP: TC75W57FK(TE85L,F); TIME: 08:44:45; UPDATEUSER: PS4_common_PC; UPDATETIME: 11:17:59; SAVECOUNT: 2; SAVEAREA0: -66604,-47529,81816,20099; OriginalSymbolOrigin: (0,0); Altium-Right: 60; Altium-Bottom: 110
pins: 1 OUTA (out), 2 INA- (in), 3 INA+ (in), 4 VSS, 5 INB+ (in), 6 INB- (in), 7 OUTB (out), 8 VDD

## TCR3UF33A
designator U?
MANUFACTURER: TOSHIBA; ITEM: IC LDO; VAL2: LDO; TIME: 08:44:48; UPDATEUSER: PS4_common_PC; UPDATETIME: 15:57:17; SAVECOUNT: 3; SAVEAREA0: -27364,-26218,44601,6573; OriginalSymbolOrigin: (0,0); Altium-Right: 70; Altium-Bottom: 80
pins: 1 VIN, 2 GND, 3 CNTRL (in), 4 NC, 5 VOUT

## TK17V65W,LQ
designator U?  VAL1: TK17V65W  (hidden comment: TK17V65W,LQ)
MANUFATURER: TOSHIBA; ITEM: FET; TIME: 08:44:45; UPDATEUSER: t5459927; SAVECOUNT: 1; OriginalSymbolOrigin: (0,0); Altium-Right: 50; Altium-Bottom: 40
pins: 1 G (in), 2 S2, 3 S3, 4 S4, 5 D

## TLP152_TPL,E
designator U?  SCH_NAME: TLP152  (hidden comment: TLP152_TPL,E)
MANUFACTURER: Toshiba; ITEM: Photocoupler; COMP: TLP152(TPL,E; TIME: 08:44:45; UPDATEUSER: t5459927; SAVECOUNT: 1; OriginalSymbolOrigin: (0,0); Altium-Right: 70; Altium-Bottom: 80
pins: 1, 3, 4, 5, 6

## TMCS1100A1QDRQ1
designator U?  VAL2: CURRENT SENSOR  (hidden comment: TMCS1100A1QDRQ1)
MANUFACTURER: TI; ITEM: IC CurrentSensor; TIME: 08:44:45; UPDATEUSER: PS4_common_PC; UPDATETIME: 16:01:14; SAVECOUNT: 3; SAVEAREA0: -10605,-15555,25377,840; OriginalSymbolOrigin: (0,0); Altium-Right: 60
pins: 1 IN+, 2 IN+, 3 IN-, 4 IN-, 5 GND, 6 VREF, 7 VOUT (out), 8 VS

## TP
designator U?  (value not drawn)
TIME: 16:12:21; UPDATEUSER: fukuda-y; UPDATETIME: 16:18:11; SAVECOUNT: 2; SAVEAREA0: -242,-92,12810,7836; OriginalSymbolOrigin: (0,7620); Altium-Right: 20; Altium-Bottom: 30
pins: 1

## TPH9R00CQ5
designator U?
MANUFACTURER: TOSHIBA; ITEM: FET; ORDER: 0; TIME: 08:44:45; UPDATEUSER: t5459927; SAVECOUNT: 1; OriginalSymbolOrigin: (0,0); Altium-Right: 60; Altium-Bottom: 40
pins: 1 S1, 2 S2, 3 S3, 4 G, 5 D1, 6 D2, 7 D3, 8 D4

## TPN7R006PL,L1Q
designator U?
MANUFACTURER: TOSHIBA; ITEM: FET; ORDER: 0; TIME: 08:44:46; UPDATEUSER: t5459927; SAVECOUNT: 1; OriginalSymbolOrigin: (0,0); Altium-Right: 60; Altium-Bottom: 40
pins: 1 S1, 2 S2, 3 S3, 4 G, 5 D1, 6 D2, 7 D3, 8 D4

## US1MDFQ_13
designator U?  VAL1: US1MDFQ-13  (hidden comment: US1MDFQ_13)
MANUFACTURER: DIODES; ITEM: DIODE; VAL2: 1000V; SIZECODESMD: 1A; TIME: 08:44:47; UPDATEUSER: t5459927; SAVECOUNT: 1; OriginalSymbolOrigin: (0,0); Altium-Right: 30; Altium-Bottom: 20
pins: A ANODE, K CATHODE

## WAKU_DEF100
designator U?  (value not drawn)
PLOTTIME: HH:MM; SAVEAREA0: 185750,-43960,448537,75779; TIME: 14:30:25; UPDATEUSER: PS4_common_PC; UPDATETIME: 14:13:01; SAVECOUNT: 8; OriginalSymbolOrigin: (10160,284480); Altium-Right: 1570; Altium-Bottom: 1070

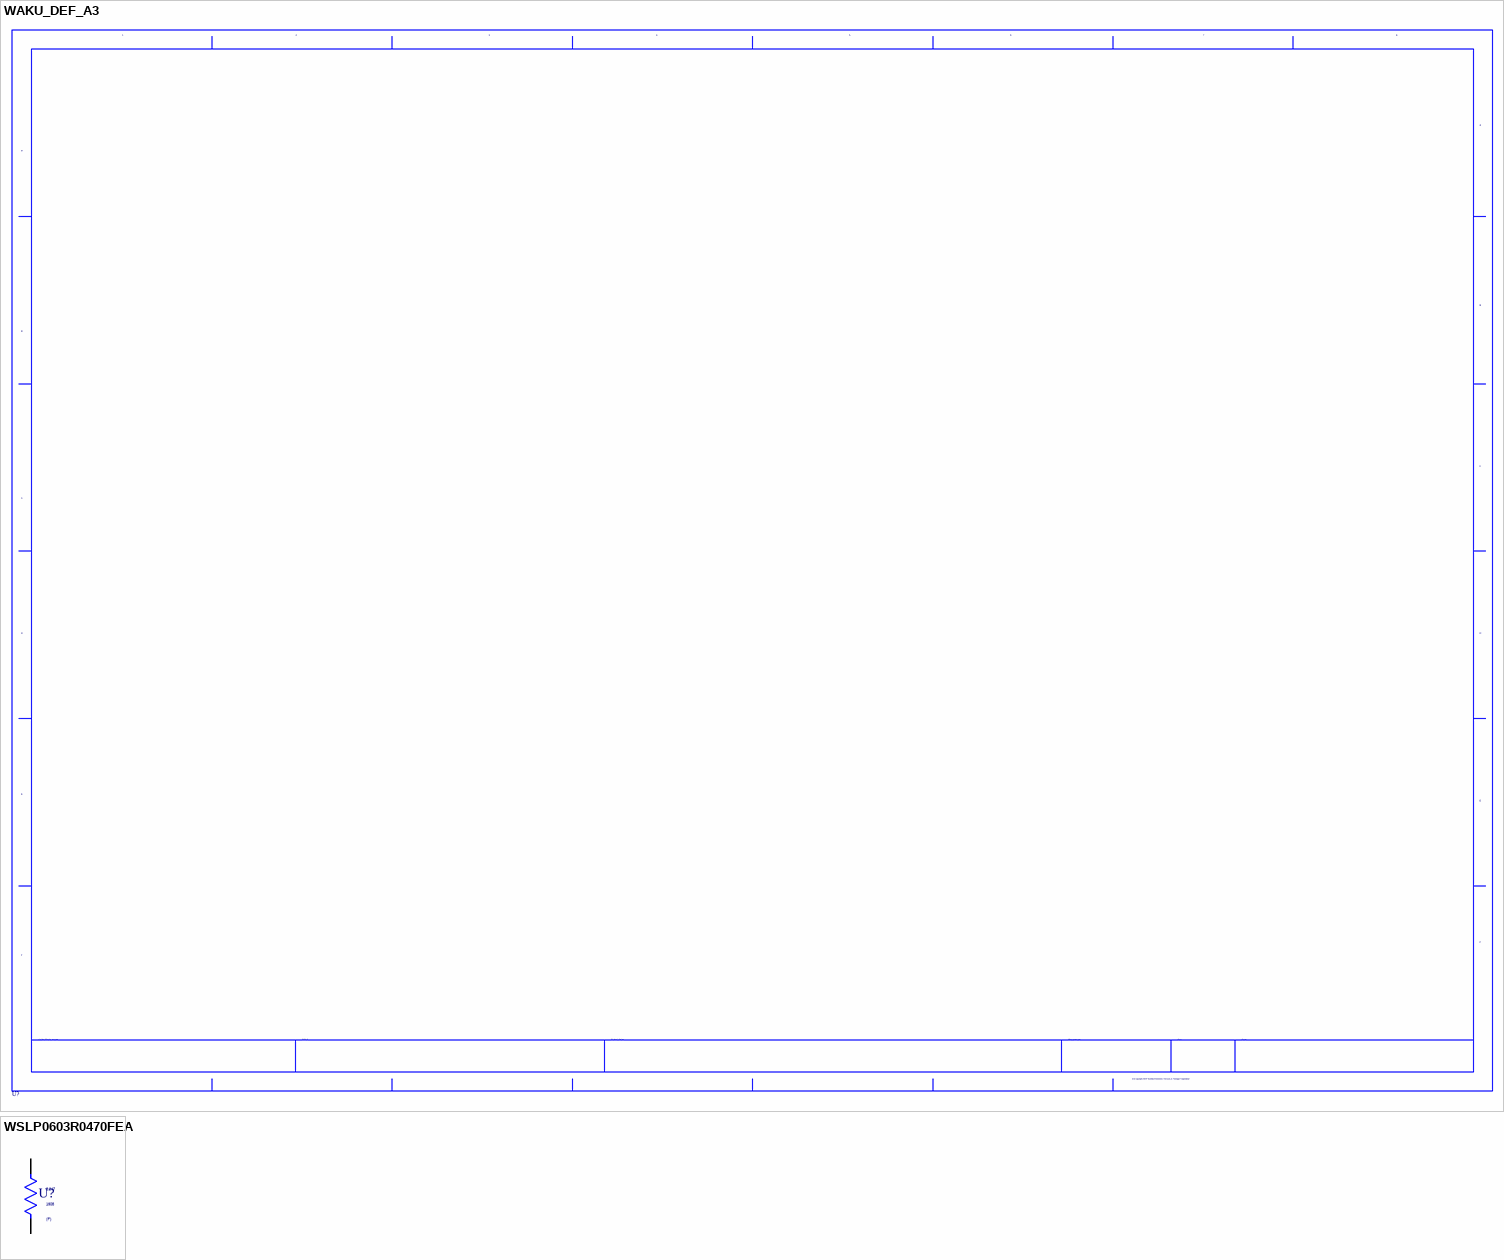
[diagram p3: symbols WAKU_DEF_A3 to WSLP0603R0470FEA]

## WAKU_DEF_A3
designator U?  (value not drawn)
PLOTTIME: HH:MM; SAVEAREA0: -311037,-554865,914355,115662; TIME: 14:30:25; UPDATEUSER: PS4_common_PC; UPDATETIME: 14:51:27; SAVECOUNT: 18; ZONEOFFSETX: 36; ZONEOFFSETY: -24; OriginalSymbolOrigin: (12700,-12700); Altium-Right: 2300; Altium-Bottom: 1650

## WSLP0603R0470FEA
designator U?  SIZECODESMD: 1608  VALUE4: (F)  VAL1: 0.047  (hidden comment: WSLP0603R0470FEA)
MANUFACTURER: Vishay; ITEM: Register; VAL2: 2/5W; TIME: 08:44:47; UPDATEUSER: t5459927; SAVECOUNT: 1; OriginalSymbolOrigin: (0,0); Altium-Right: 20; Altium-Bottom: 30
pins: 1, 2

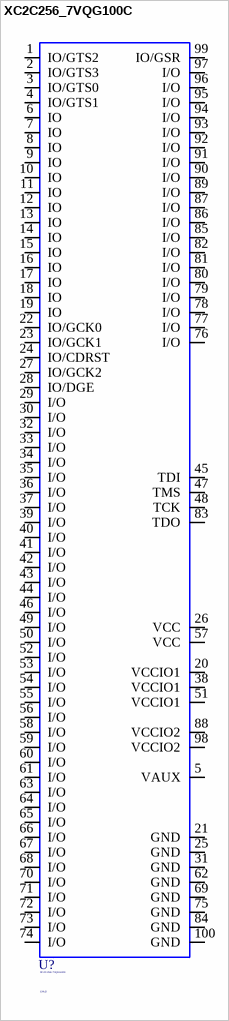
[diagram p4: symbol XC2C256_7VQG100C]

## XC2C256_7VQG100C
designator U?  VAL2: CPLD  VAL1: XC2C256-7VQG100C  (hidden comment: XC2C256_7VQG100C)
MANUFACTURER: Xilinx; ITEM: IC CPLD; TIME: 08:44:46; UPDATEUSER: PS4_common_PC; UPDATETIME: 16:00:18; SAVECOUNT: 3; SAVEAREA0: -110321,-158692,133213,-47724; OriginalSymbolOrigin: (0,0); Altium-Right: 100; Altium-Bottom: 610
pins: 1 IO/GTS2, 2 IO/GTS3, 3 IO/GTS0, 4 IO/GTS1, 5 VAUX, 6 IO, 7 IO, 8 IO, 9 IO, 10 IO, 11 IO, 12 IO, 13 IO, 14 IO, 15 IO, 16 IO, 17 IO, 18 IO, 19 IO, 20 VCCIO1, 21 GND, 22 IO/GCK0, 23 IO/GCK1, 24 IO/CDRST, 25 GND, 26 VCC, 27 IO/GCK2, 28 IO/DGE, 29 I/O, 30 I/O, 31 GND, 32 I/O, 33 I/O, 34 I/O, 35 I/O, 36 I/O, 37 I/O, 38 VCCIO1, 39 I/O, 40 I/O, 41 I/O, 42 I/O, 43 I/O, 44 I/O, 45 TDI, 46 I/O, 47 TMS, 48 TCK, 49 I/O, 50 I/O, 51 VCCIO1, 52 I/O, 53 I/O, 54 I/O, 55 I/O, 56 I/O, 57 VCC, 58 I/O, 59 I/O, 60 I/O, 61 I/O, 62 GND, 63 I/O, 64 I/O, 65 I/O, 66 I/O, 67 I/O, 68 I/O, 69 GND, 70 I/O, 71 I/O, 72 I/O, 73 I/O, 74 I/O, 75 GND, 76 I/O, 77 I/O, 78 I/O, 79 I/O, 80 I/O, 81 I/O, 82 I/O, 83 TDO, 84 GND, 85 I/O, 86 I/O, 87 I/O, 88 VCCIO2, 89 I/O, 90 I/O, 91 I/O, 92 I/O, 93 I/O, 94 I/O, 95 I/O, 96 I/O, 97 I/O, 98 VCCIO2, 99 IO/GSR, 100 GND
